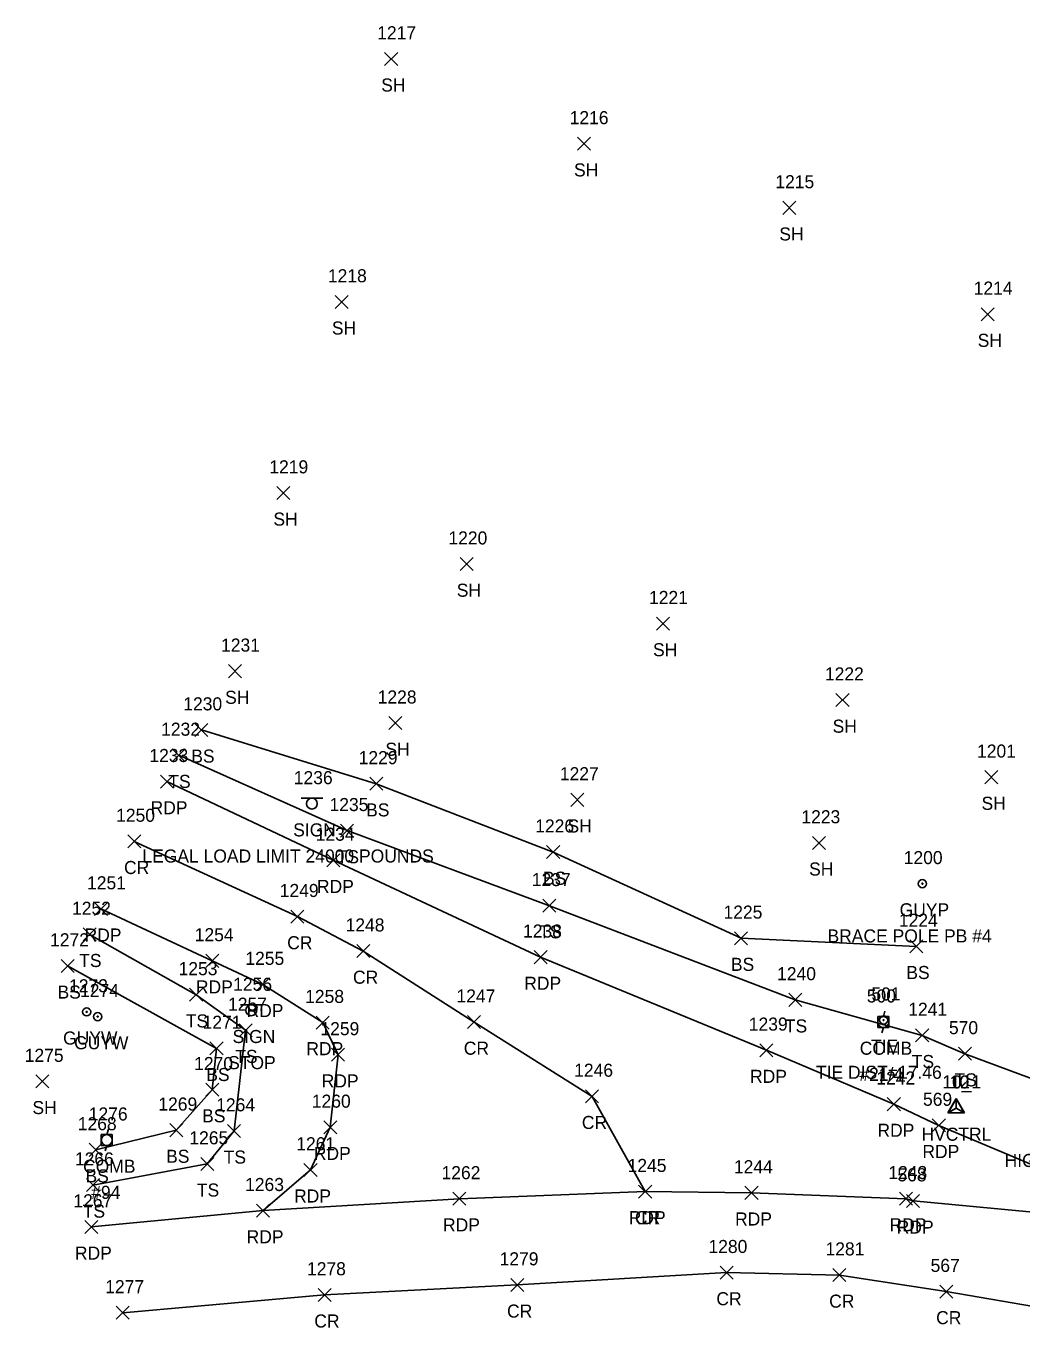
# Model space of a CAD drawing. Extents: x 1485624 to 1495982, y 886445 to 890805.
# Drawn here: x 1495473.8 to 1495626.2, y 890605.4 to 890804.8 of the extents above; entities that cross this region are included whole.
import ezdxf

# ---------------------------------------------------------------- set-up
doc = ezdxf.new("R2010")
doc.units = 0
for name, color, linetype in [('C_A', 7, 'Continuous'), ('C_C', 7, 'Continuous'), ('C_I', 7, 'Continuous'), ('CBP', 7, 'Continuous'), ('CPSM', 7, 'Continuous'), ('L_A', 7, 'Continuous'), ('L_I', 7, 'Continuous'), ('L_TIC', 7, 'Continuous'), ('LELB', 7, 'Continuous'), ('P_A', 7, 'Continuous'), ('P_I', 7, 'Continuous'), ('P_TIC', 7, 'Continuous'), ('PET', 7, 'Continuous'), ('PRC', 7, 'Continuous'), ('S_A', 7, 'Continuous'), ('S_C', 7, 'Continuous'), ('S_I', 7, 'Continuous'), ('SSGN', 7, 'Continuous'), ('U_A', 7, 'Continuous'), ('U_C', 7, 'Continuous'), ('U_I', 7, 'Continuous'), ('UP', 7, 'Continuous'), ('UPGW', 7, 'Continuous')]:
    doc.layers.add(name, color=color, linetype=linetype)

msp = doc.modelspace()

# ---------------------------------------------------------------- linework, layer by layer
at = {"layer": 'CBP'}
for radius in [0.625, 0.0833]:
    msp.add_circle((1495605.06, 890652.58), radius, dxfattribs=at)
at = {"layer": 'CPSM'}
for p, q in [((1495614.91, 890638.38), (1495616.16, 890640.55)), ((1495614.92, 890638.38), (1495616.17, 890640.55)), ((1495614.92, 890638.38), (1495616.17, 890640.54)), ((1495617.41, 890638.38), (1495616.16, 890640.55)), ((1495616.16, 890639.1), (1495616.16, 890640.55)), ((1495617.42, 890638.38), (1495616.17, 890640.55)), ((1495616.17, 890639.1), (1495616.17, 890640.55)), ((1495617.42, 890638.38), (1495616.17, 890640.54)), ((1495616.17, 890639.1), (1495616.17, 890640.54)), ((1495614.91, 890638.38), (1495616.16, 890639.1)), ((1495614.91, 890638.38), (1495617.41, 890638.38)), ((1495614.92, 890638.38), (1495616.17, 890639.1)), ((1495614.92, 890638.38), (1495616.17, 890639.1)), ((1495614.92, 890638.38), (1495617.42, 890638.38)), ((1495614.92, 890638.38), (1495617.42, 890638.38)), ((1495616.16, 890639.1), (1495616.16, 890639.1)), ((1495616.16, 890639.1), (1495617.41, 890638.38)), ((1495616.17, 890639.1), (1495616.17, 890639.1)), ((1495616.17, 890639.1), (1495617.42, 890638.38)), ((1495616.17, 890639.1), (1495616.17, 890639.1)), ((1495616.17, 890639.1), (1495617.42, 890638.38))]:
    msp.add_line(p, q, dxfattribs=at)
at = {"layer": 'L_TIC'}
for points in [[(1495528.69, 890798.76), (1495530.69, 890800.76)], [(1495530.69, 890798.76), (1495528.69, 890800.76)], [(1495558.19, 890785.76), (1495560.19, 890787.76)], [(1495560.19, 890785.76), (1495558.19, 890787.76)], [(1495589.62, 890775.95), (1495591.62, 890777.95)], [(1495591.62, 890775.95), (1495589.62, 890777.95)], [(1495521.13, 890761.55), (1495523.13, 890763.55)], [(1495523.13, 890761.55), (1495521.13, 890763.55)], [(1495619.97, 890759.66), (1495621.97, 890761.66)], [(1495621.97, 890759.66), (1495619.97, 890761.66)], [(1495512.18, 890732.29), (1495514.18, 890734.29)], [(1495514.18, 890732.29), (1495512.18, 890734.29)], [(1495540.24, 890721.4), (1495542.24, 890723.4)], [(1495542.24, 890721.4), (1495540.24, 890723.4)], [(1495570.29, 890712.29), (1495572.29, 890714.29)], [(1495572.29, 890712.29), (1495570.29, 890714.29)], [(1495504.79, 890705), (1495506.79, 890707)], [(1495506.79, 890705), (1495504.79, 890707)], [(1495597.77, 890700.58), (1495599.77, 890702.58)], [(1495599.77, 890700.58), (1495597.77, 890702.58)], [(1495499.66, 890696), (1495501.66, 890698)], [(1495501.66, 890696), (1495499.66, 890698)], [(1495529.33, 890697.05), (1495531.33, 890699.05)], [(1495531.33, 890697.05), (1495529.33, 890699.05)], [(1495496.18, 890692.12), (1495498.18, 890694.12)], [(1495498.18, 890692.12), (1495496.18, 890694.12)], [(1495526.42, 890687.76), (1495528.42, 890689.76)], [(1495528.42, 890687.76), (1495526.42, 890689.76)], [(1495620.56, 890688.77), (1495622.56, 890690.77)], [(1495622.56, 890688.77), (1495620.56, 890690.77)], [(1495557.2, 890685.3), (1495559.2, 890687.3)], [(1495559.2, 890685.3), (1495557.2, 890687.3)], [(1495521.95, 890680.58), (1495523.95, 890682.58)], [(1495523.95, 890680.58), (1495521.95, 890682.58)], [(1495594.17, 890678.71), (1495596.17, 890680.71)], [(1495596.17, 890678.71), (1495594.17, 890680.71)], [(1495553.49, 890677.3), (1495555.49, 890679.3)], [(1495555.49, 890677.3), (1495553.49, 890679.3)], [(1495552.91, 890669.09), (1495554.91, 890671.09)], [(1495554.91, 890669.09), (1495552.91, 890671.09)], [(1495482.54, 890664.7), (1495484.54, 890666.7)], [(1495484.54, 890664.7), (1495482.54, 890666.7)], [(1495582.25, 890664.11), (1495584.25, 890666.11)], [(1495584.25, 890664.11), (1495582.25, 890666.11)], [(1495609.09, 890662.86), (1495611.09, 890664.86)], [(1495611.09, 890662.86), (1495609.09, 890664.86)], [(1495479.18, 890659.87), (1495481.18, 890661.87)], [(1495481.18, 890659.87), (1495479.18, 890661.87)], [(1495498.85, 890655.45), (1495500.85, 890657.45)], [(1495500.85, 890655.45), (1495498.85, 890657.45)], [(1495590.54, 890654.68), (1495592.54, 890656.68)], [(1495592.54, 890654.68), (1495590.54, 890656.68)], [(1495506.42, 890650.01), (1495508.42, 890652.01)], [(1495508.42, 890650.01), (1495506.42, 890652.01)], [(1495609.96, 890649.23), (1495611.96, 890651.23)], [(1495611.96, 890649.23), (1495609.96, 890651.23)], [(1495501.96, 890647.24), (1495503.96, 890649.24)], [(1495503.96, 890647.24), (1495501.96, 890649.24)], [(1495616.51, 890646.42), (1495618.51, 890648.42)], [(1495618.51, 890646.42), (1495616.51, 890648.42)], [(1495475.3, 890642.18), (1495477.3, 890644.18)], [(1495477.3, 890642.18), (1495475.3, 890644.18)], [(1495501.32, 890640.92), (1495503.32, 890642.92)], [(1495503.32, 890640.92), (1495501.32, 890642.92)], [(1495495.81, 890634.72), (1495497.81, 890636.72)], [(1495497.81, 890634.72), (1495495.81, 890636.72)], [(1495504.65, 890634.6), (1495506.65, 890636.6)], [(1495506.65, 890634.6), (1495504.65, 890636.6)], [(1495483.47, 890631.71), (1495485.47, 890633.71)], [(1495485.47, 890631.71), (1495483.47, 890633.71)], [(1495500.55, 890629.55), (1495502.55, 890631.55)], [(1495502.55, 890629.55), (1495500.55, 890631.55)], [(1495483.08, 890626.32), (1495485.08, 890628.32)], [(1495485.08, 890626.32), (1495483.08, 890628.32)]]:
    msp.add_lwpolyline(points, dxfattribs=at)
at = {"layer": 'LELB'}
for points in [[(1495610.09, 890663.86), (1495583.25, 890665.11), (1495554.49, 890678.3), (1495527.42, 890688.76), (1495500.66, 890697)], [(1495497.18, 890693.12), (1495522.95, 890681.58), (1495553.91, 890670.09), (1495591.54, 890655.68), (1495610.96, 890650.23)], [(1495483.54, 890665.7), (1495499.85, 890656.45), (1495507.42, 890651.01), (1495505.65, 890635.6), (1495501.55, 890630.55), (1495484.08, 890627.32)], [(1495484.47, 890632.71), (1495496.81, 890635.72), (1495502.32, 890641.92), (1495502.96, 890648.24), (1495480.18, 890660.87)], [(1495617.51, 890647.42), (1495610.96, 890650.23)], [(1495617.51, 890647.42), (1495659.25, 890631.91), (1495662.58, 890630.34), (1495680.12, 890623), (1495718.11, 890611.07), (1495750.98, 890602.51), (1495783.18, 890591.68), (1495810.94, 890582.07), (1495845.91, 890568.15), (1495889.08, 890548.91)]]:
    msp.add_lwpolyline(points, dxfattribs=at)
at = {"layer": 'P_TIC'}
for points in [[(1495494.38, 890688.09), (1495496.38, 890690.09)], [(1495496.38, 890688.09), (1495494.38, 890690.09)], [(1495489.38, 890678.94), (1495491.38, 890680.94)], [(1495491.38, 890678.94), (1495489.38, 890680.94)], [(1495519.84, 890676.04), (1495521.84, 890678.04)], [(1495521.84, 890676.04), (1495519.84, 890678.04)], [(1495484.28, 890668.6), (1495486.28, 890670.6)], [(1495486.28, 890668.6), (1495484.28, 890670.6)], [(1495514.34, 890667.42), (1495516.34, 890669.42)], [(1495516.34, 890667.42), (1495514.34, 890669.42)], [(1495524.42, 890662.14), (1495526.42, 890664.14)], [(1495526.42, 890662.14), (1495524.42, 890664.14)], [(1495501.32, 890660.65), (1495503.32, 890662.65)], [(1495503.32, 890660.65), (1495501.32, 890662.65)], [(1495551.57, 890661.21), (1495553.57, 890663.21)], [(1495553.57, 890661.21), (1495551.57, 890663.21)], [(1495509.07, 890657.03), (1495511.07, 890659.03)], [(1495511.07, 890657.03), (1495509.07, 890659.03)], [(1495518.22, 890651.2), (1495520.22, 890653.2)], [(1495520.22, 890651.2), (1495518.22, 890653.2)], [(1495541.38, 890651.27), (1495543.38, 890653.27)], [(1495543.38, 890651.27), (1495541.38, 890653.27)], [(1495520.57, 890646.26), (1495522.57, 890648.26)], [(1495522.57, 890646.26), (1495520.57, 890648.26)], [(1495586.13, 890646.96), (1495588.13, 890648.96)], [(1495588.13, 890646.96), (1495586.13, 890648.96)], [(1495559.45, 890639.9), (1495561.45, 890641.9)], [(1495561.45, 890639.9), (1495559.45, 890641.9)], [(1495605.63, 890638.7), (1495607.63, 890640.7)], [(1495607.63, 890638.7), (1495605.63, 890640.7)], [(1495519.37, 890635.16), (1495521.37, 890637.16)], [(1495521.37, 890635.16), (1495519.37, 890637.16)], [(1495612.51, 890635.45), (1495614.51, 890637.45)], [(1495614.51, 890635.45), (1495612.51, 890637.45)], [(1495516.35, 890628.64), (1495518.35, 890630.64)], [(1495518.35, 890628.64), (1495516.35, 890630.64)], [(1495539.14, 890624.21), (1495541.14, 890626.21)], [(1495541.14, 890624.21), (1495539.14, 890626.21)], [(1495567.57, 890625.32), (1495569.57, 890627.32)], [(1495569.57, 890625.32), (1495567.57, 890627.32)], [(1495567.57, 890625.32), (1495569.57, 890627.32)], [(1495569.57, 890625.32), (1495567.57, 890627.32)], [(1495583.84, 890625.12), (1495585.84, 890627.12)], [(1495585.84, 890625.12), (1495583.84, 890627.12)], [(1495607.48, 890624.23), (1495609.48, 890626.23)], [(1495609.48, 890624.23), (1495607.48, 890626.23)], [(1495608.58, 890623.88), (1495610.58, 890625.88)], [(1495610.58, 890623.88), (1495608.58, 890625.88)], [(1495509.08, 890622.4), (1495511.08, 890624.4)], [(1495511.08, 890622.4), (1495509.08, 890624.4)], [(1495509.08, 890622.4), (1495511.08, 890624.4)], [(1495511.08, 890622.4), (1495509.08, 890624.4)], [(1495482.8, 890619.9), (1495484.8, 890621.9)], [(1495484.8, 890619.9), (1495482.8, 890621.9)], [(1495580.04, 890612.91), (1495582.04, 890614.91)], [(1495582.04, 890612.91), (1495580.04, 890614.91)], [(1495597.29, 890612.54), (1495599.29, 890614.54)], [(1495599.29, 890612.54), (1495597.29, 890614.54)], [(1495548, 890611.02), (1495550, 890613.02)], [(1495550, 890611.02), (1495548, 890613.02)], [(1495613.66, 890610.01), (1495615.66, 890612.01)], [(1495615.66, 890610.01), (1495613.66, 890612.01)], [(1495518.5, 890609.5), (1495520.5, 890611.5)], [(1495520.5, 890609.5), (1495518.5, 890611.5)], [(1495487.62, 890606.76), (1495489.62, 890608.76)], [(1495489.62, 890606.76), (1495487.62, 890608.76)]]:
    msp.add_lwpolyline(points, dxfattribs=at)
at = {"layer": 'PET'}
for points in [[(1495495.38, 890689.09), (1495520.84, 890677.04), (1495552.57, 890662.21), (1495587.13, 890647.96), (1495606.63, 890639.7)], [(1495485.28, 890669.6), (1495502.32, 890661.65), (1495510.07, 890658.03), (1495519.22, 890652.2), (1495521.57, 890647.26), (1495520.37, 890636.16), (1495517.35, 890629.64), (1495510.08, 890623.4)], [(1495613.51, 890636.45), (1495606.63, 890639.7)], [(1495613.51, 890636.45), (1495650.02, 890621.06)], [(1495608.48, 890625.23), (1495584.84, 890626.12), (1495568.57, 890626.32), (1495540.14, 890625.21), (1495510.08, 890623.4), (1495483.8, 890620.9)], [(1495609.58, 890624.88), (1495608.48, 890625.23)], [(1495609.58, 890624.88), (1495650.02, 890621.06), (1495682.45, 890614.6), (1495716.9, 890606.52), (1495749.59, 890597.76), (1495779.95, 890588.14), (1495810.5, 890576.96), (1495843, 890563.53), (1495882.78, 890545.01)]]:
    msp.add_lwpolyline(points, dxfattribs=at)
at = {"layer": 'PRC'}
for points in [[(1495568.57, 890626.32), (1495560.45, 890640.9), (1495542.38, 890652.27), (1495525.42, 890663.14), (1495515.34, 890668.42), (1495490.38, 890679.94)], [(1495488.62, 890607.76), (1495519.5, 890610.5), (1495549, 890612.02), (1495581.04, 890613.91), (1495598.29, 890613.54)], [(1495614.66, 890611.01), (1495598.29, 890613.54)], [(1495865.85, 890538.25), (1495835.89, 890551.78), (1495804.87, 890564.57), (1495770.54, 890576.59), (1495737.23, 890586.26), (1495702.08, 890594.9), (1495658.63, 890603.44), (1495614.66, 890611.01)]]:
    msp.add_lwpolyline(points, dxfattribs=at)
at = {"layer": 'SSGN'}
for p, q in [((1495515.91, 890686.56), (1495519.25, 890686.56)), ((1495517.56, 890685.72), (1495517.56, 890685.72)), ((1495506.63, 890654.91), (1495509.97, 890654.91)), ((1495508.28, 890654.08), (1495508.28, 890654.08))]:
    msp.add_line(p, q, dxfattribs=at)
for centre in [(1495517.56, 890685.72), (1495508.28, 890654.08)]:
    msp.add_circle(centre, 0.833, dxfattribs=at)
at = {"layer": 'UP'}
for p, q in [((1495605.27, 890653.94), (1495605.02, 890653.1)), ((1495604.19, 890651.44), (1495604.19, 890653.1)), ((1495604.19, 890653.1), (1495605.85, 890653.1)), ((1495605.02, 890652.27), (1495605.02, 890652.27)), ((1495605.85, 890653.1), (1495605.85, 890651.44)), ((1495605.85, 890651.44), (1495604.19, 890651.44)), ((1495604.77, 890650.6), (1495605.02, 890651.44)), ((1495486.41, 890635.87), (1495486.16, 890635.04)), ((1495485.32, 890633.37), (1495485.32, 890635.04)), ((1495485.32, 890635.04), (1495486.99, 890635.04)), ((1495486.16, 890634.2), (1495486.16, 890634.2)), ((1495486.99, 890635.04), (1495486.99, 890633.37)), ((1495486.99, 890633.37), (1495485.32, 890633.37)), ((1495485.91, 890632.54), (1495486.16, 890633.37))]:
    msp.add_line(p, q, dxfattribs=at)
for centre in [(1495605.02, 890652.27), (1495486.16, 890634.2)]:
    msp.add_circle(centre, 0.833, dxfattribs=at)
at = {"layer": 'UPGW'}
for centre, radius in [((1495611, 890673.46), 0.625), ((1495611, 890673.46), 0.0833), ((1495483.09, 890653.83), 0.625), ((1495483.09, 890653.83), 0.0833), ((1495484.77, 890653.11), 0.625), ((1495484.77, 890653.11), 0.0833)]:
    msp.add_circle(centre, radius, dxfattribs=at)

# ---------------------------------------------------------------- texts
at = {"layer": 'C_A'}
for s, p in [('TIE', (1495603.14, 890647.58)), ('HVCTRL', (1495610.86, 890634.1)), ('HVCTRL', (1495610.86, 890634.1)), ('HVCTRL', (1495610.86, 890634.1))]:
    msp.add_text(s, height=2, dxfattribs=at).set_placement(p)
at = {"layer": 'C_C'}
msp.add_text('TIE DIST=17.46', height=2, dxfattribs=at).set_placement((1495594.71, 890643.58))
at = {"layer": 'C_I'}
for s, p in [('501', (1495603.19, 890655.58)), ('10_1', (1495614.04, 890642.1)), ('10', (1495615.19, 890642.1)), ('12', (1495615.27, 890642.1))]:
    msp.add_text(s, height=2, dxfattribs=at).set_placement(p)
at = {"layer": 'L_A'}
for s, p in [('SH', (1495528.17, 890794.76)), ('SH', (1495557.68, 890781.76)), ('SH', (1495589.1, 890771.95)), ('SH', (1495520.62, 890757.55)), ('SH', (1495619.46, 890755.66)), ('SH', (1495511.67, 890728.29)), ('SH', (1495539.73, 890717.4)), ('SH', (1495569.77, 890708.29)), ('SH', (1495504.28, 890701)), ('SH', (1495597.26, 890696.58)), ('BS', (1495499.1, 890692)), ('SH', (1495528.81, 890693.05)), ('TS', (1495495.59, 890688.12)), ('BS', (1495525.86, 890683.76)), ('SH', (1495620.05, 890684.77)), ('SH', (1495556.69, 890681.3)), ('TS', (1495521.36, 890676.58)), ('SH', (1495593.66, 890674.71)), ('BS', (1495552.93, 890673.3)), ('TS', (1495552.32, 890665.09)), ('TS', (1495481.95, 890660.7)), ('BS', (1495581.69, 890660.11)), ('BS', (1495608.54, 890658.86)), ('BS', (1495478.63, 890655.87)), ('TS', (1495498.26, 890651.45)), ('TS', (1495589.95, 890650.68)), ('TS', (1495505.83, 890646.01)), ('TS', (1495609.37, 890645.23)), ('BS', (1495501.4, 890643.24)), ('TS', (1495615.92, 890642.42)), ('SH', (1495474.79, 890638.18)), ('BS', (1495500.76, 890636.92)), ('BS', (1495495.25, 890630.72)), ('TS', (1495504.06, 890630.6)), ('BS', (1495482.91, 890627.71)), ('TS', (1495499.96, 890625.55)), ('TS', (1495482.49, 890622.32))]:
    msp.add_text(s, height=2, dxfattribs=at).set_placement(p)
at = {"layer": 'L_I'}
for s, p in [('1217', (1495527.56, 890802.76)), ('1216', (1495557.01, 890789.76)), ('1215', (1495588.49, 890779.95)), ('1218', (1495520.01, 890765.55)), ('1214', (1495618.85, 890763.66)), ('1219', (1495511.05, 890736.29)), ('1220', (1495538.46, 890725.4)), ('1221', (1495569.16, 890716.29)), ('1231', (1495503.66, 890709)), ('1222', (1495596.08, 890704.58)), ('1230', (1495497.88, 890700)), ('1228', (1495527.63, 890701.05)), ('1232', (1495494.49, 890696.12)), ('1229', (1495524.72, 890691.76)), ('1201', (1495619.36, 890692.77)), ('1227', (1495555.51, 890689.3)), ('1235', (1495520.26, 890684.58)), ('1223', (1495592.48, 890682.71)), ('1226', (1495551.74, 890681.3)), ('1237', (1495551.22, 890673.09)), ('1252', (1495480.85, 890668.7)), ('1225', (1495580.56, 890668.11)), ('1224', (1495607.4, 890666.86)), ('1272', (1495477.49, 890663.87)), ('1253', (1495497.16, 890659.45)), ('1240', (1495588.76, 890658.68)), ('1257', (1495504.73, 890654.01)), ('1241', (1495608.83, 890653.23)), ('1271', (1495500.83, 890651.24)), ('570', (1495615.06, 890650.42)), ('1275', (1495473.61, 890646.18)), ('1270', (1495499.54, 890644.92)), ('1269', (1495494.06, 890638.72)), ('1264', (1495502.91, 890638.6)), ('1268', (1495481.73, 890635.71)), ('1265', (1495498.81, 890633.55)), ('1266', (1495481.29, 890630.32))]:
    msp.add_text(s, height=2, dxfattribs=at).set_placement(p)
at = {"layer": 'P_A'}
for s, p in [('RDP', (1495492.87, 890684.09)), ('CR', (1495488.81, 890674.94)), ('RDP', (1495518.33, 890672.04)), ('RDP', (1495482.77, 890664.6)), ('CR', (1495513.78, 890663.42)), ('CR', (1495523.85, 890658.14)), ('RDP', (1495499.81, 890656.65)), ('RDP', (1495550.06, 890657.21)), ('RDP', (1495507.56, 890653.03)), ('RDP', (1495516.71, 890647.2)), ('CR', (1495540.81, 890647.27)), ('RDP', (1495519.06, 890642.26)), ('RDP', (1495584.62, 890642.96)), ('CR', (1495558.88, 890635.9)), ('RDP', (1495604.12, 890634.7)), ('RDP', (1495517.86, 890631.16)), ('RDP', (1495611, 890631.45)), ('RDP', (1495514.84, 890624.64)), ('RDP', (1495537.63, 890620.21)), ('RDP', (1495566.06, 890621.32)), ('CR', (1495567, 890621.32)), ('RDP', (1495582.33, 890621.12)), ('RDP', (1495605.97, 890620.23)), ('RDP', (1495607.07, 890619.88)), ('RDP', (1495507.57, 890618.4)), ('RDP', (1495507.57, 890618.4)), ('RDP', (1495481.29, 890615.9)), ('CR', (1495579.47, 890608.91)), ('CR', (1495596.73, 890608.54)), ('CR', (1495547.43, 890607.02)), ('CR', (1495613.1, 890606.01)), ('CR', (1495517.93, 890605.5))]:
    msp.add_text(s, height=2, dxfattribs=at).set_placement(p)
at = {"layer": 'P_I'}
for s, p in [('1233', (1495492.69, 890692.09)), ('1250', (1495487.6, 890682.94)), ('1234', (1495518.14, 890680.04)), ('1251', (1495483.15, 890672.6)), ('1249', (1495512.64, 890671.42)), ('1248', (1495522.72, 890666.14)), ('1254', (1495499.63, 890664.65)), ('1238', (1495549.88, 890665.21)), ('1255', (1495507.38, 890661.03)), ('1258', (1495516.53, 890655.2)), ('1247', (1495539.69, 890655.27)), ('1259', (1495518.87, 890650.26)), ('1239', (1495584.43, 890650.96)), ('1246', (1495557.7, 890643.9)), ('1242', (1495603.94, 890642.7)), ('1260', (1495517.55, 890639.16)), ('569', (1495611.09, 890639.45)), ('1261', (1495515.17, 890632.64)), ('1262', (1495537.4, 890628.21)), ('1245', (1495565.88, 890629.32)), ('1245', (1495565.88, 890629.32)), ('1244', (1495582.15, 890629.12)), ('1243', (1495605.79, 890628.23)), ('568', (1495607.17, 890627.88)), ('1263', (1495507.34, 890626.4)), ('1263', (1495507.34, 890626.4)), ('1267', (1495481.06, 890623.9)), ('1280', (1495578.26, 890616.91)), ('1281', (1495596.17, 890616.54)), ('1279', (1495546.29, 890615.02)), ('567', (1495612.25, 890614.01)), ('1278', (1495516.81, 890613.5)), ('1277', (1495485.93, 890610.76))]:
    msp.add_text(s, height=2, dxfattribs=at).set_placement(p)
at = {"layer": 'S_A'}
for p in [(1495514.7, 890680.7), (1495505.42, 890649.06)]:
    msp.add_text('SIGN', height=2, dxfattribs=at).set_placement(p)
at = {"layer": 'S_C'}
for s, p in [('LEGAL LOAD LIMIT 24000 POUNDS', (1495491.62, 890676.7)), ('STOP', (1495504.74, 890645.06)), ('HIGHGATE SPRINGS', (1495623.58, 890630.08))]:
    msp.add_text(s, height=2, dxfattribs=at).set_placement(p)
at = {"layer": 'S_I'}
for s, p in [('1236', (1495514.79, 890688.7)), ('1256', (1495505.51, 890657.06))]:
    msp.add_text(s, height=2, dxfattribs=at).set_placement(p)
at = {"layer": 'U_A'}
for s, p in [('GUYP', (1495607.51, 890668.46)), ('GUYW', (1495479.48, 890648.83)), ('GUYW', (1495481.17, 890648.11)), ('COMB', (1495601.41, 890647.27)), ('COMB', (1495482.54, 890629.2))]:
    msp.add_text(s, height=2, dxfattribs=at).set_placement(p)
at = {"layer": 'U_C'}
for s, p in [('BRACE POLE PB #4', (1495596.48, 890664.46)), ('#21/4', (1495601.35, 890643.27)), ('#94', (1495483.79, 890625.2))]:
    msp.add_text(s, height=2, dxfattribs=at).set_placement(p)
at = {"layer": 'U_I'}
for s, p in [('1200', (1495608.14, 890676.46)), ('1273', (1495480.4, 890656.83)), ('1274', (1495482.08, 890656.11)), ('500', (1495602.49, 890655.27)), ('1276', (1495483.41, 890637.2))]:
    msp.add_text(s, height=2, dxfattribs=at).set_placement(p)

doc.saveas('drawing.dxf')
